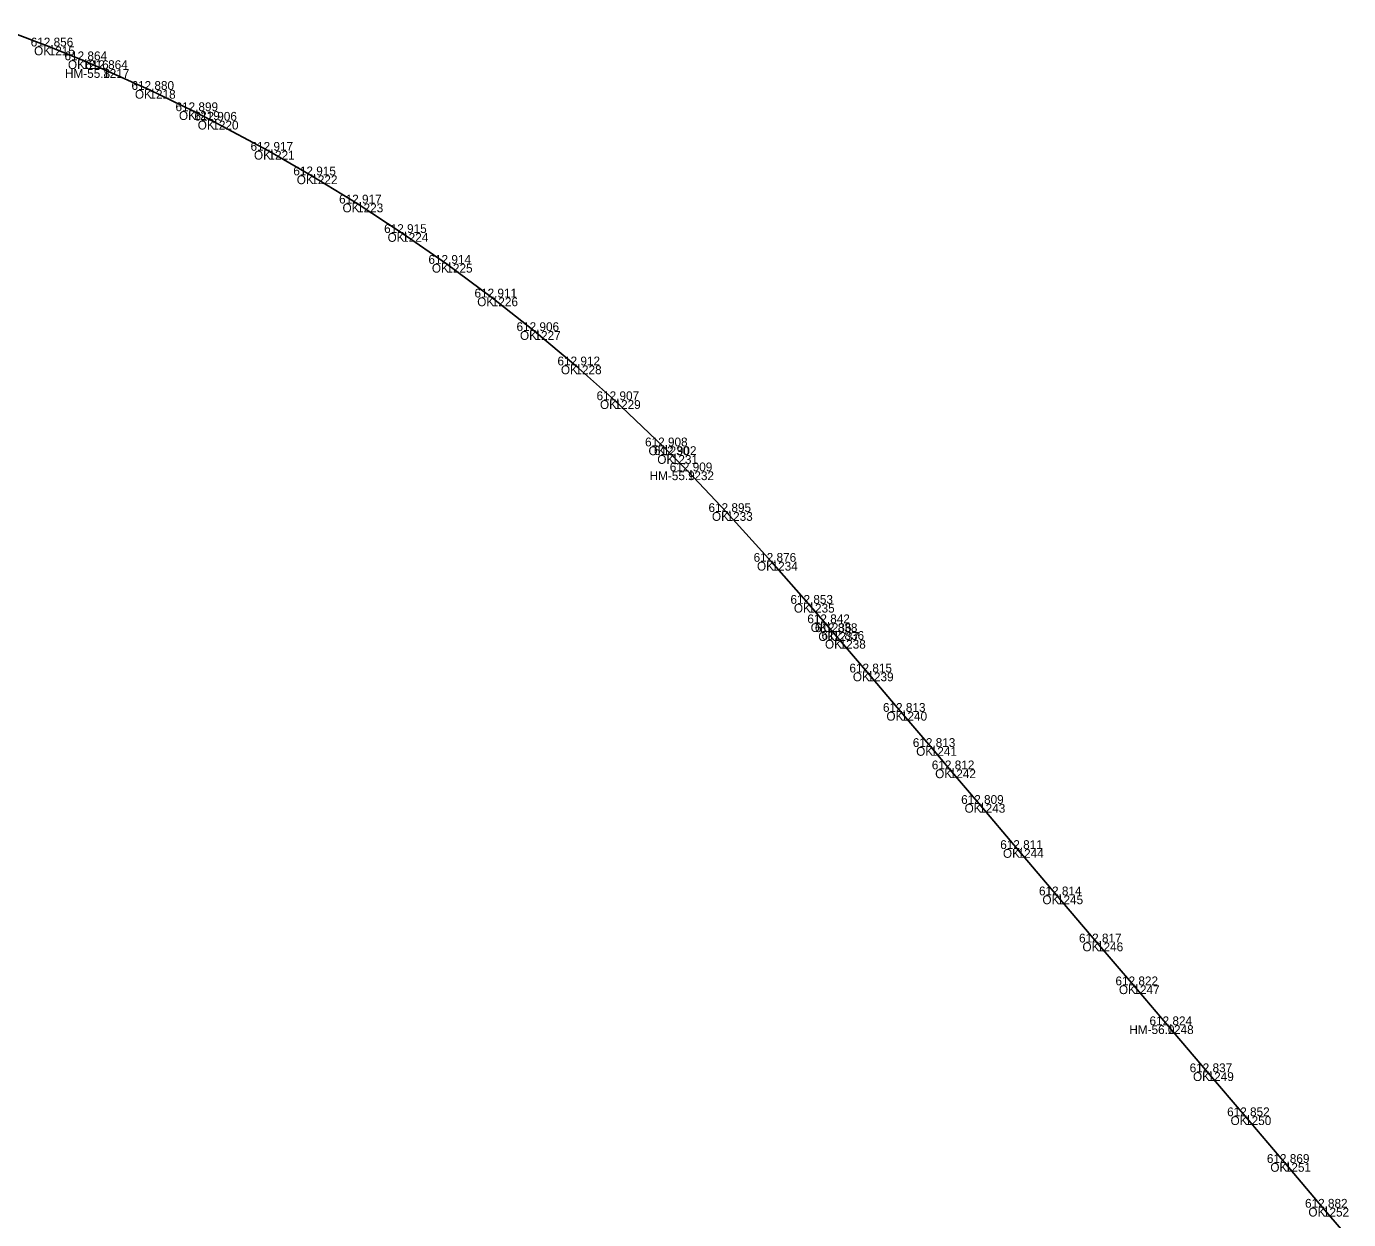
# Model space of a CAD drawing. Extents: x -631472 to -620808, y -1122356 to -1115125.
# Drawn here: x -625466.3 to -625286, y -1118247.1 to -1118084.5 of the extents above; entities that cross this region are included whole.
import ezdxf

# ---------------------------------------------------------------- set-up
doc = ezdxf.new("R2010")
doc.units = 0
for name, color, linetype in [('Vrstva 1', 7, 'Continuous'), ('Vrstva 60', 7, 'Continuous'), ('Vrstva 61', 7, 'Continuous'), ('Vrstva 62', 7, 'Continuous')]:
    doc.layers.add(name, color=color, linetype=linetype)

msp = doc.modelspace()

# ---------------------------------------------------------------- linework, layer by layer
at = {"layer": 'Vrstva 1'}
msp.add_lwpolyline([(-625470.44, -1118084.48), (-625463.23, -1118087.21), (-625458.62, -1118089.09), (-625455.8, -1118090.29), (-625449.49, -1118093.13), (-625443.48, -1118096.03), (-625440.92, -1118097.33), (-625433.26, -1118101.43), (-625427.43, -1118104.78), (-625421.19, -1118108.62), (-625415.04, -1118112.64), (-625409.01, -1118116.84), (-625402.82, -1118121.43), (-625397, -1118126.01), (-625391.42, -1118130.69), (-625386.09, -1118135.43), (-625379.47, -1118141.73), (-625378.28, -1118142.91), (-625376.1, -1118145.13), (-625370.82, -1118150.68), (-625364.68, -1118157.46), (-625359.65, -1118163.19), (-625357.36, -1118165.84), (-625356.32, -1118167.05), (-625355.41, -1118168.1), (-625351.62, -1118172.55), (-625347.05, -1118177.92), (-625342.98, -1118182.71), (-625340.39, -1118185.76), (-625336.39, -1118190.47), (-625331.15, -1118196.62), (-625325.78, -1118202.94), (-625320.32, -1118209.36), (-625315.35, -1118215.2), (-625310.71, -1118220.64), (-625305.24, -1118227.05), (-625300.13, -1118233.05), (-625294.71, -1118239.42), (-625289.52, -1118245.52), (-625286.77, -1118248.75)], dxfattribs=at)
at = {"layer": 'Vrstva 60'}
for p, q in [((-625463.23, -1118087.21), (-625463.23, -1118087.21)), ((-625458.62, -1118089.09), (-625458.62, -1118089.09)), ((-625455.8, -1118090.29), (-625455.8, -1118090.29)), ((-625449.49, -1118093.13), (-625449.49, -1118093.13)), ((-625443.48, -1118096.03), (-625443.48, -1118096.03)), ((-625440.92, -1118097.33), (-625440.92, -1118097.33)), ((-625433.26, -1118101.43), (-625433.26, -1118101.43)), ((-625427.43, -1118104.78), (-625427.43, -1118104.78)), ((-625421.19, -1118108.62), (-625421.19, -1118108.62)), ((-625415.04, -1118112.64), (-625415.04, -1118112.64)), ((-625409.01, -1118116.84), (-625409.01, -1118116.84)), ((-625402.82, -1118121.43), (-625402.82, -1118121.43)), ((-625397, -1118126.01), (-625397, -1118126.01)), ((-625391.42, -1118130.69), (-625391.42, -1118130.69)), ((-625386.09, -1118135.43), (-625386.09, -1118135.43)), ((-625379.47, -1118141.73), (-625379.47, -1118141.73)), ((-625378.28, -1118142.91), (-625378.28, -1118142.91)), ((-625376.1, -1118145.13), (-625376.1, -1118145.13)), ((-625370.82, -1118150.68), (-625370.82, -1118150.68)), ((-625364.68, -1118157.46), (-625364.68, -1118157.46)), ((-625359.65, -1118163.19), (-625359.65, -1118163.19)), ((-625357.36, -1118165.84), (-625357.36, -1118165.84)), ((-625356.32, -1118167.05), (-625356.32, -1118167.05)), ((-625355.41, -1118168.1), (-625355.41, -1118168.1)), ((-625351.62, -1118172.55), (-625351.62, -1118172.55)), ((-625347.05, -1118177.92), (-625347.05, -1118177.92)), ((-625342.98, -1118182.71), (-625342.98, -1118182.71)), ((-625340.39, -1118185.76), (-625340.39, -1118185.76)), ((-625336.39, -1118190.47), (-625336.39, -1118190.47)), ((-625331.15, -1118196.62), (-625331.15, -1118196.62)), ((-625325.78, -1118202.94), (-625325.78, -1118202.94)), ((-625320.32, -1118209.36), (-625320.32, -1118209.36)), ((-625315.35, -1118215.2), (-625315.35, -1118215.2)), ((-625310.71, -1118220.64), (-625310.71, -1118220.64)), ((-625305.24, -1118227.05), (-625305.24, -1118227.05)), ((-625300.13, -1118233.05), (-625300.13, -1118233.05)), ((-625294.71, -1118239.42), (-625294.71, -1118239.42)), ((-625289.52, -1118245.52), (-625289.52, -1118245.52))]:
    msp.add_line(p, q, dxfattribs=at)

# ---------------------------------------------------------------- texts
for s, p in [('1215', (-625463.23, -1118088.41)), ('1216', (-625458.62, -1118090.29)), ('1217', (-625455.8, -1118091.49)), ('1218', (-625449.49, -1118094.33)), ('1219', (-625443.48, -1118097.23)), ('1220', (-625440.92, -1118098.53)), ('1221', (-625433.26, -1118102.63)), ('1222', (-625427.43, -1118105.98)), ('1223', (-625421.19, -1118109.82)), ('1224', (-625415.04, -1118113.84)), ('1225', (-625409.01, -1118118.04)), ('1226', (-625402.82, -1118122.62)), ('1227', (-625397, -1118127.21)), ('1228', (-625391.42, -1118131.89)), ('1229', (-625386.09, -1118136.63)), ('1230', (-625379.47, -1118142.93)), ('1231', (-625378.28, -1118144.11)), ('1232', (-625376.1, -1118146.33)), ('1233', (-625370.82, -1118151.88)), ('1234', (-625364.68, -1118158.66)), ('1235', (-625359.65, -1118164.39)), ('1236', (-625357.36, -1118167.04)), ('1237', (-625356.32, -1118168.25)), ('1238', (-625355.41, -1118169.3)), ('1239', (-625351.62, -1118173.75)), ('1240', (-625347.05, -1118179.12)), ('1241', (-625342.98, -1118183.91)), ('1242', (-625340.39, -1118186.96)), ('1243', (-625336.39, -1118191.67)), ('1244', (-625331.15, -1118197.82)), ('1245', (-625325.78, -1118204.14)), ('1246', (-625320.32, -1118210.56)), ('1247', (-625315.35, -1118216.4)), ('1248', (-625310.71, -1118221.84)), ('1249', (-625305.24, -1118228.25)), ('1250', (-625300.13, -1118234.25)), ('1251', (-625294.71, -1118240.62)), ('1252', (-625289.52, -1118246.72))]:
    msp.add_text(s, height=1.2, dxfattribs=at).set_placement(p)
at = {"layer": 'Vrstva 61'}
for s, p in [('612.856', (-625465.68, -1118087.21)), ('612.864', (-625461.07, -1118089.09)), ('612.864', (-625458.25, -1118090.29)), ('612.880', (-625451.94, -1118093.13)), ('612.899', (-625445.94, -1118096.03)), ('612.906', (-625443.37, -1118097.33)), ('612.917', (-625435.71, -1118101.43)), ('612.915', (-625429.88, -1118104.78)), ('612.917', (-625423.64, -1118108.62)), ('612.915', (-625417.5, -1118112.64)), ('612.914', (-625411.46, -1118116.84)), ('612.911', (-625405.18, -1118121.43)), ('612.906', (-625399.45, -1118126.01)), ('612.912', (-625393.87, -1118130.69)), ('612.907', (-625388.54, -1118135.43)), ('612.908', (-625381.93, -1118141.73)), ('612.902', (-625380.72, -1118142.91)), ('612.909', (-625378.56, -1118145.13)), ('612.895', (-625373.28, -1118150.68)), ('612.876', (-625367.13, -1118157.46)), ('612.853', (-625362.11, -1118163.19)), ('612.842', (-625359.81, -1118165.84)), ('612.838', (-625358.78, -1118167.05)), ('612.836', (-625357.87, -1118168.1)), ('612.815', (-625354.07, -1118172.55)), ('612.813', (-625349.5, -1118177.92)), ('612.813', (-625345.43, -1118182.71)), ('612.812', (-625342.84, -1118185.76)), ('612.809', (-625338.84, -1118190.47)), ('612.811', (-625333.51, -1118196.62)), ('612.814', (-625328.23, -1118202.94)), ('612.817', (-625322.77, -1118209.36)), ('612.822', (-625317.8, -1118215.2)), ('612.824', (-625313.16, -1118220.64)), ('612.837', (-625307.69, -1118227.05)), ('612.852', (-625302.58, -1118233.05)), ('612.869', (-625297.16, -1118239.42)), ('612.882', (-625291.96, -1118245.52))]:
    msp.add_text(s, height=1.2, dxfattribs=at).set_placement(p)
at = {"layer": 'Vrstva 62'}
for s, p in [('OK', (-625465.22, -1118088.41)), ('HM-55.8', (-625461.01, -1118091.49)), ('OK', (-625460.6, -1118090.29)), ('OK', (-625451.47, -1118094.33)), ('OK', (-625445.47, -1118097.23)), ('OK', (-625442.91, -1118098.53)), ('OK', (-625435.24, -1118102.63)), ('OK', (-625429.41, -1118105.98)), ('OK', (-625423.17, -1118109.82)), ('OK', (-625417.03, -1118113.84)), ('OK', (-625410.99, -1118118.04)), ('OK', (-625404.81, -1118122.62)), ('OK', (-625398.98, -1118127.21)), ('OK', (-625393.4, -1118131.89)), ('OK', (-625388.07, -1118136.63)), ('OK', (-625381.46, -1118142.93)), ('OK', (-625380.26, -1118144.11)), ('HM-55.9', (-625381.31, -1118146.33)), ('OK', (-625372.81, -1118151.88)), ('OK', (-625366.67, -1118158.66)), ('OK', (-625361.64, -1118164.39)), ('OK', (-625359.35, -1118167.04)), ('OK', (-625358.31, -1118168.25)), ('OK', (-625357.4, -1118169.3)), ('OK', (-625353.6, -1118173.75)), ('OK', (-625349.03, -1118179.12)), ('OK', (-625344.97, -1118183.91)), ('OK', (-625342.38, -1118186.96)), ('OK', (-625338.37, -1118191.67)), ('OK', (-625333.14, -1118197.82)), ('OK', (-625327.76, -1118204.14)), ('OK', (-625322.3, -1118210.56)), ('OK', (-625317.33, -1118216.4)), ('HM-56.0', (-625315.91, -1118221.84)), ('OK', (-625307.23, -1118228.25)), ('OK', (-625302.11, -1118234.25)), ('OK', (-625296.69, -1118240.62)), ('OK', (-625291.5, -1118246.72))]:
    msp.add_text(s, height=1.2, dxfattribs=at).set_placement(p)

doc.saveas('drawing.dxf')
